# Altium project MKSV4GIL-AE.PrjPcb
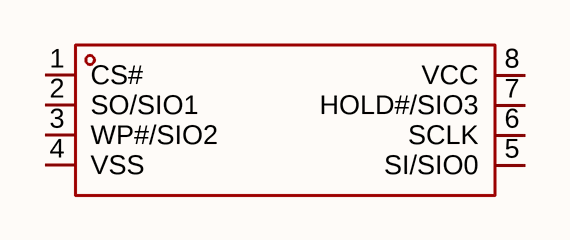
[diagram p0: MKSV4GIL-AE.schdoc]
1 sheet, 1 parts. Net scope: global (net labels, ports and power ports of the same name join across sheets).

## Sheet MKSV4GIL-AE.schdoc
size 127 x 101 mm

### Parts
U?  mksv4gil-ae  [LGA-8_L6.0-W8.0-P1.27-BL_MKSV4G-8GIL-AET]  (value not drawn)

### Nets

Not connected (* = marked no-connect by the designer): U? 1(CS#) 2(SO/SIO1) 3(WP#/SIO2) 4(VSS) 5(SI/SIO0) 6(SCLK) 7(HOLD#/SIO3) 8(VCC)

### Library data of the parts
U? = mksv4gil-ae: 存储容量:4Gbit;时钟频率(fc):104MHz;工作电压:2.7V~3.6V;; Manufacturer: MK(米客方德); AddInBom: yes; ModelId: 1a9f17e09c6f4a21b77c65e0dae63c20; ModelName: LGA-8_L6.0-W8.0-H0.8-P1.27-BL_MKSV4G_8GIL-AET; ModelTransform: 314.96,236.22,0,90,0,0,0,0,0; Memory Size: 4Gbit; Interface: SPI; Clock Frequency: 104MHz; Block Erase Time(tBE): 3ms; Data Retention - TDR (Year): 10年; Standby Supply Current: 65uA; Program / Erase Cycles: 10万次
